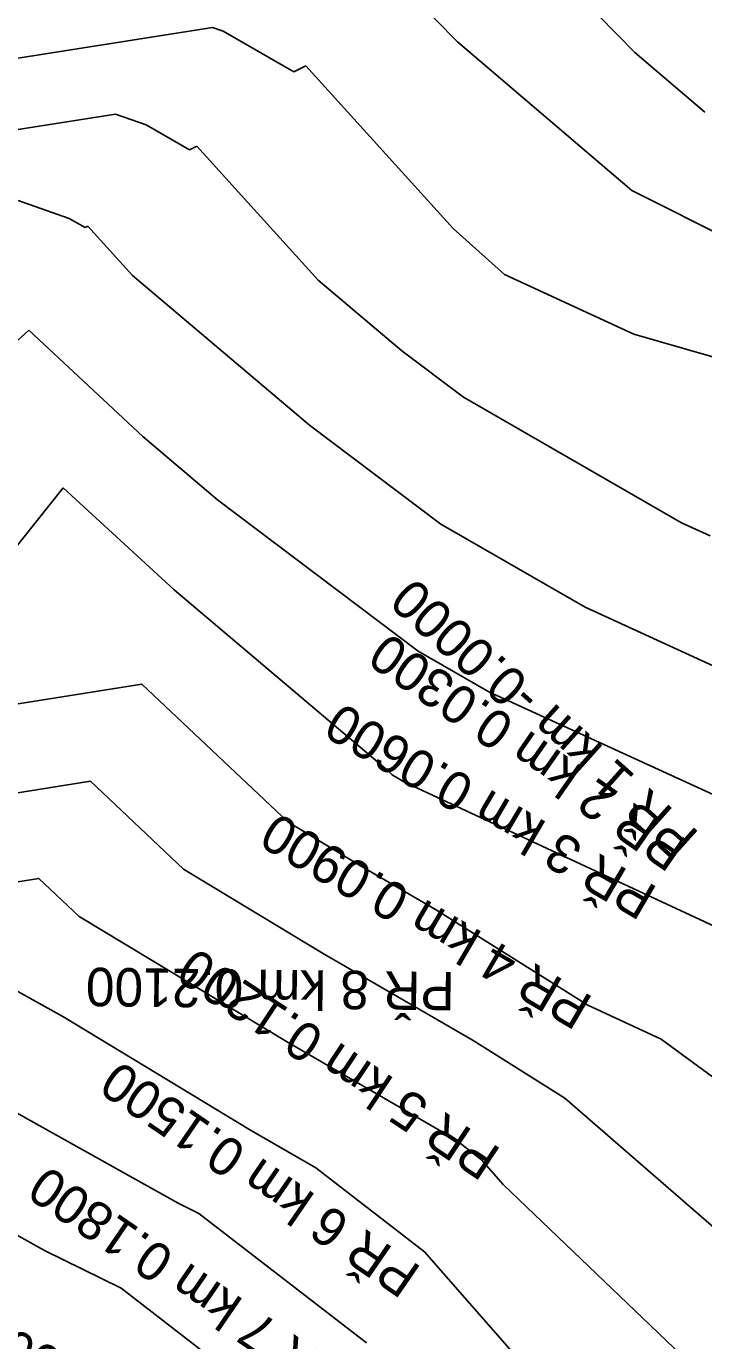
# Model space of a CAD drawing. Extents: x -549394 to -546608, y -1037055 to -1033629.
# Drawn here: x -548731.3 to -548571.7, y -1034624 to -1034314.2 of the extents above; entities that cross this region are included whole.
import ezdxf

# ---------------------------------------------------------------- set-up
doc = ezdxf.new("R2010")
doc.units = 0
for name, color, linetype in [('hlavni_vrst', 7, 'Continuous'), ('norm_vrst', 7, 'Continuous'), ('x_popis_pricne_rezy_C123', 7, 'Continuous')]:
    doc.layers.add(name, color=color, linetype=linetype)

msp = doc.modelspace()

# ---------------------------------------------------------------- linework, layer by layer
at = {"layer": 'hlavni_vrst'}
for p, q in [((-548629.71, -1034317.92), (-548645.86, -1034301.43)), ((-548588.64, -1034352.94), (-548629.71, -1034317.92)), ((-548549.58, -1034372.48), (-548588.64, -1034352.94)), ((-548722.62, -1034422.98), (-548748.38, -1034455.32)), ((-548696.43, -1034447.05), (-548722.62, -1034422.98)), ((-548646.53, -1034489.27), (-548696.43, -1034447.05)), ((-548645.09, -1034490.62), (-548646.53, -1034489.27)), ((-548644.45, -1034491.01), (-548645.09, -1034490.62)), ((-548643.76, -1034491.42), (-548644.45, -1034491.01)), ((-548642.37, -1034492.28), (-548643.76, -1034491.42)), ((-548558.63, -1034531.2), (-548642.37, -1034492.28)), ((-548695.5, -1034591.58), (-548752.79, -1034559.55)), ((-548690.63, -1034593.97), (-548695.5, -1034591.58)), ((-548651.16, -1034624.47), (-548690.63, -1034593.97))]:
    msp.add_line(p, q, dxfattribs=at)
at = {"layer": 'norm_vrst'}
for p, q in [((-548587.9, -1034320.42), (-548630.1, -1034277.34)), ((-548687.4, -1034314.52), (-548740.71, -1034322.92)), ((-548684.92, -1034315.39), (-548687.4, -1034314.52)), ((-548668.27, -1034324.97), (-548684.92, -1034315.39)), ((-548571.43, -1034334.47), (-548587.9, -1034320.42)), ((-548665.39, -1034323.55), (-548668.27, -1034324.97)), ((-548630.74, -1034361.88), (-548665.39, -1034323.55)), ((-548710.3, -1034334.9), (-548740.22, -1034339.62)), ((-548703.04, -1034337.46), (-548710.3, -1034334.9)), ((-548692.84, -1034343.32), (-548703.04, -1034337.46)), ((-548691.08, -1034342.45), (-548692.84, -1034343.32)), ((-548662.5, -1034374.07), (-548691.08, -1034342.45)), ((-548721.16, -1034359.52), (-548733.19, -1034355.28)), ((-548717.42, -1034361.68), (-548721.16, -1034359.52)), ((-548716.77, -1034361.36), (-548717.42, -1034361.68)), ((-548706.28, -1034372.96), (-548716.77, -1034361.36)), ((-548618.59, -1034372.71), (-548630.74, -1034361.88)), ((-548664.52, -1034408.24), (-548706.28, -1034372.96)), ((-548588.13, -1034386.75), (-548618.59, -1034372.71)), ((-548642.83, -1034390.68), (-548662.5, -1034374.07)), ((-548730.72, -1034385.83), (-548745.9, -1034399.75)), ((-548703.81, -1034410.93), (-548730.72, -1034385.83)), ((-548557.36, -1034395.67), (-548588.13, -1034386.75)), ((-548628.29, -1034401.66), (-548642.83, -1034390.68)), ((-548576.92, -1034431.22), (-548628.29, -1034401.66)), ((-548686.2, -1034425.81), (-548703.81, -1034410.93)), ((-548633.63, -1034431.57), (-548664.52, -1034408.24)), ((-548638.98, -1034461.47), (-548686.2, -1034425.81)), ((-548599.62, -1034451.14), (-548633.63, -1034431.57)), ((-548570.13, -1034434.34), (-548576.92, -1034431.22)), ((-548563.3, -1034467.8), (-548599.62, -1034451.14)), ((-548622.32, -1034471.06), (-548638.98, -1034461.47)), ((-548704.09, -1034469.25), (-548770.74, -1034479.84)), ((-548669.67, -1034501.74), (-548704.09, -1034469.25)), ((-548556.48, -1034501.26), (-548622.32, -1034471.06)), ((-548716.19, -1034492.14), (-548758.7, -1034498.89)), ((-548694.25, -1034512.86), (-548716.19, -1034492.14)), ((-548652.96, -1034511.84), (-548669.67, -1034501.74)), ((-548661.47, -1034532.67), (-548694.25, -1034512.86)), ((-548634.88, -1034522.34), (-548652.96, -1034511.84)), ((-548728.3, -1034515.03), (-548746.65, -1034517.95)), ((-548718.82, -1034523.98), (-548728.3, -1034515.03)), ((-548599, -1034544.88), (-548634.88, -1034522.34)), ((-548669.98, -1034553.5), (-548718.82, -1034523.98)), ((-548626.01, -1034553.26), (-548661.47, -1034532.67)), ((-548722.7, -1034547.61), (-548740.46, -1034537.68)), ((-548581.72, -1034552.91), (-548599, -1034544.88)), ((-548678.49, -1034574.33), (-548722.7, -1034547.61)), ((-548604.37, -1034566.86), (-548626.01, -1034553.26)), ((-548565.77, -1034564.64), (-548581.72, -1034552.91)), ((-548630.11, -1034576.64), (-548669.98, -1034553.5)), ((-548566.94, -1034599.32), (-548604.37, -1034566.86)), ((-548663.08, -1034583.27), (-548678.49, -1034574.33)), ((-548624.04, -1034581.32), (-548630.11, -1034576.64)), ((-548618.9, -1034587.2), (-548624.04, -1034581.32)), ((-548727, -1034602.74), (-548765.13, -1034581.42)), ((-548637.45, -1034603.02), (-548663.08, -1034583.27)), ((-548571.95, -1034632.13), (-548618.9, -1034587.2)), ((-548708.94, -1034611.58), (-548727, -1034602.74)), ((-548615.69, -1034627.87), (-548637.45, -1034603.02)), ((-548680.02, -1034633.92), (-548708.94, -1034611.58))]:
    msp.add_line(p, q, dxfattribs=at)

# ---------------------------------------------------------------- texts
at = {"layer": 'x_popis_pricne_rezy_C123'}
for s, rotation, p in [('PŘ 1 km -0.0000', 138.1192, (-548572.43, -1034504.47)), ('PŘ 2 km 0.0300', 145.1827, (-548574.86, -1034506.43)), ('PŘ 3 km 0.0600', 149.6, (-548582.2, -1034517.34)), ('PŘ 4 km 0.0900', 149.6, (-548597.38, -1034543.22)), ('PŘ 5 km 0.1200', 146.4847, (-548619.06, -1034579.04)), ('PŘ 8 km 0.2100', 179.3159, (-548630.29, -1034537.09)), ('PŘ 6 km 0.1500', 145.5454, (-548637.86, -1034606.87)), ('PŘ 7 km 0.1800', 145.5454, (-548654.83, -1034631.61)), ('PŘ 9 km 0.2400', 154.1143, (-548656.24, -1034658.77))]:
    msp.add_text(s, height=9.0627, rotation=rotation, dxfattribs=at).set_placement(p)

doc.saveas('drawing.dxf')
